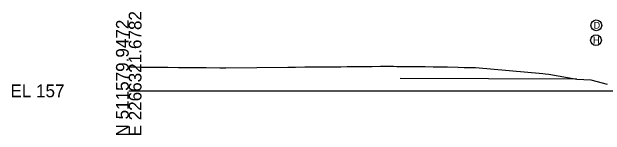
# Model space of a CAD drawing. Extents: x -516 to 303, y -10 to 5017.
# Drawn here: x -25.7 to 104.7, y 3490.3 to 3517.3 of the extents above; entities that cross this region are included whole.
import ezdxf

# ---------------------------------------------------------------- set-up
doc = ezdxf.new("R2010")
doc.units = 0
for name, color, linetype in [('Default', 7, 'Continuous'), ('Exist Cross Section Cell', 7, 'Continuous'), ('Exist XS Ground Line', 7, 'Continuous'), ('Prop Road Sect_ Material - Bubble + Leader + Bubble Tx', 7, 'Continuous'), ('Prop Road Sect_ Material - Contact (General - Major)', 7, 'Continuous'), ('Prop Road Sect_ Material - Tx (Composite Desc)', 7, 'Continuous')]:
    doc.layers.add(name, color=color, linetype=linetype)

msp = doc.modelspace()

# ---------------------------------------------------------------- linework, layer by layer
at = {"layer": 'Exist Cross Section Cell'}
msp.add_line((0, 3500), (150, 3500), dxfattribs=at)
at = {"layer": 'Exist XS Ground Line'}
msp.add_lwpolyline([(0, 3505.24), (0.6, 3505.24), (1.55, 3505.23), (2.43, 3505.22), (2.95, 3505.21), (4.98, 3505.2), (5.84, 3505.19), (6.47, 3505.19), (8.57, 3505.18), (10.94, 3505.1), (17.06, 3505.09), (20.01, 3505.06), (21.34, 3505.05), (34.95, 3505.19), (36.64, 3505.21), (38.69, 3505.23), (42.12, 3505.27), (42.62, 3505.27), (42.92, 3505.27), (43.77, 3505.26), (45.57, 3505.28), (46.2, 3505.29), (46.62, 3505.29), (48.05, 3505.32), (49.54, 3505.34), (49.89, 3505.34), (50.48, 3505.35), (52.42, 3505.37), (53.52, 3505.37), (55.36, 3505.38), (56.99, 3505.38), (57.54, 3505.38), (58.2, 3505.38), (58.97, 3505.37), (60.27, 3505.36), (60.81, 3505.36), (61.13, 3505.35), (62.39, 3505.34), (64.03, 3505.33), (64.45, 3505.32), (65.16, 3505.31), (66.92, 3505.28), (68.27, 3505.26), (70.07, 3505.24), (72.44, 3505.22), (73.73, 3505.15), (75.52, 3505.08), (76.27, 3505.1), (91.06, 3503.79), (91.59, 3503.75), (92.36, 3503.62), (98.5, 3502.59), (101.62, 3502.41), (105.17, 3501.45)], dxfattribs=at)
at = {"layer": 'Prop Road Sect_ Material - Bubble + Leader + Bubble Tx'}
for centre in [(102.8, 3514.35), (102.73, 3511.1)]:
    msp.add_circle(centre, 1.18, dxfattribs=at)
at = {"layer": 'Prop Road Sect_ Material - Contact (General - Major)'}
msp.add_line((98.5, 3502.59), (59.71, 3502.73), dxfattribs=at)

# ---------------------------------------------------------------- texts
at = {"layer": 'Default'}
msp.add_text('-', height=0.0001, dxfattribs=at).set_placement((0, 3500))
at = {"layer": 'Exist Cross Section Cell'}
for s, p in [('E 2266321.6782', (2.8, 3490)), ('N 511579.9472', (0, 3490))]:
    msp.add_text(s, height=2.8, rotation=90, dxfattribs=at).set_placement(p)
msp.add_text('EL 157', height=2.8, dxfattribs=at).set_placement((-26, 3498.6))
at = {"layer": 'Prop Road Sect_ Material - Tx (Composite Desc)'}
for s, p in [('D', (102.2, 3513.62)), ('H', (102.08, 3510.37))]:
    msp.add_text(s, height=1.5, dxfattribs=at).set_placement(p)

doc.saveas('drawing.dxf')
